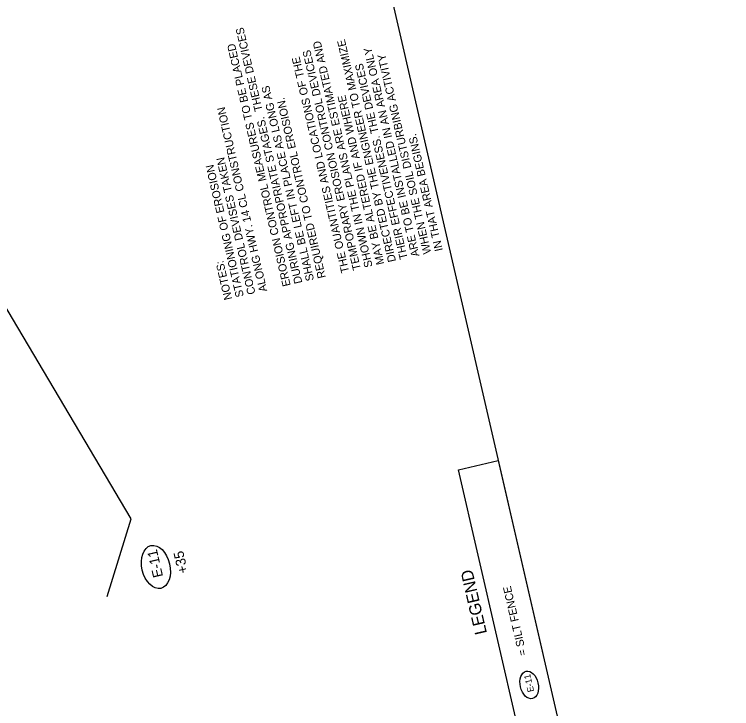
# Model space of a CAD drawing. Extents: x 634644 to 1109343, y 286699 to 700411.
# Drawn here: x 1108806 to 1109343, y 699423 to 699943 of the extents above; entities that cross this region are included whole.
import ezdxf

# ---------------------------------------------------------------- set-up
doc = ezdxf.new("R2010")
doc.units = 0
for name, color, linetype in [('S_BASELINE', 7, 'Continuous'), ('S_PRIMARY_CTL', 7, 'Continuous'), ('XSEC_P_Ditch-and-Channel-Line', 7, 'Continuous')]:
    doc.layers.add(name, color=color, linetype=linetype)

msp = doc.modelspace()

# ---------------------------------------------------------------- linework, layer by layer
at = {"layer": 'S_BASELINE'}
msp.add_lwpolyline([(1109343.25, 698851.3), (1108342.28, 698620.21), (1108052.69, 699874.57), (1108100.82, 699885.68), (1108030.37, 700190.85), (1108983.2, 700410.83)], close=True, dxfattribs=at)
at = {"layer": 'S_PRIMARY_CTL'}
for p, q in [((1109138.71, 699601.57), (1109168.45, 699608.43)), ((1109168.45, 699608.43), (1109213.35, 699413.94)), ((1109183.62, 699407.07), (1109138.71, 699601.57))]:
    msp.add_line(p, q, dxfattribs=at)
msp.add_ellipse((1109191.62, 699440.56), major_axis=(-2.37, 10.25), ratio=0.638788, dxfattribs=at)
at = {"layer": 'XSEC_P_Ditch-and-Channel-Line'}
for p, q in [((1108893.39, 699564.81), (1108783.45, 699750.14)), ((1108875.45, 699506.74), (1108893.39, 699564.81))]:
    msp.add_line(p, q, dxfattribs=at)
msp.add_ellipse((1108911.95, 699528.84), major_axis=(-3.71, 16.01), ratio=0.638788, dxfattribs=at)

# ---------------------------------------------------------------- texts
at = {"layer": 'S_PRIMARY_CTL'}
for s, height, p in [('DURING APPROPRIATE STAGES.  THESE DEVICES', 6, (1109021.68, 699741.6)), ('SHOWN IN THE PLANS ARE ESTIMATED AND ', 6, (1109074.3, 699753.75)), ('DIRECTED BY THE ENGINEER TO MAXIMIZE ', 6, (1109091.84, 699757.8)), ('EROSION CONTROL MEASURES TO BE PLACED', 6, (1109012.91, 699739.58)), ('TEMPORARY EROSION CONTROL DEVICES', 6, (1109065.53, 699751.73)), ('ARE TO BE INSTALLED IN AN AREA ONLY ', 6, (1109109.38, 699761.85)), ('WHEN THE SOIL DISTURBING ACTIVITY', 6, (1109118.15, 699763.87)), ('THE OUANTITIES AND LOCATIONS OF THE ', 6, (1109056.76, 699749.7)), ('THEIR EFFECTIVENESS. THE DEVICES', 6, (1109100.61, 699759.83)), ('SHALL BE LEFT IN PLACE AS LONG AS', 6, (1109030.45, 699743.63)), ('REQUIRED TO CONTROL EROSION.', 6, (1109039.22, 699745.65)), ('MAY BE ALTERED IF AND WHERE', 6, (1109083.07, 699755.78)), ('ALONG HWY. 14 CL CONSTRUCTION', 6, (1108995.38, 699735.53)), ('IN THAT AREA BEGINS.', 6, (1109126.92, 699765.9)), ('CONTROL DEVISES TAKEN', 6, (1108986.61, 699733.51)), ('STATIONING OF EROSION', 6, (1108977.84, 699731.48)), ('NOTES:', 6, (1108969.07, 699729.46)), ('LEGEND', 9, (1109159.99, 699479.33)), ('LEGEND', 9, (1109159.99, 699479.33)), ('= SILT FENCE', 6, (1109189.7, 699463.14)), ('E-11', 4.8, (1109195.29, 699435.8))]:
    msp.add_text(s, height=height, rotation=103, dxfattribs=at).set_placement(p)
at = {"layer": 'XSEC_P_Ditch-and-Channel-Line'}
for s, p in [('E-11', (1108917.36, 699521.85)), ('+35', (1108936.1, 699524.87))]:
    msp.add_text(s, height=7.499, rotation=103.0379, dxfattribs=at).set_placement(p)

doc.saveas('drawing.dxf')
